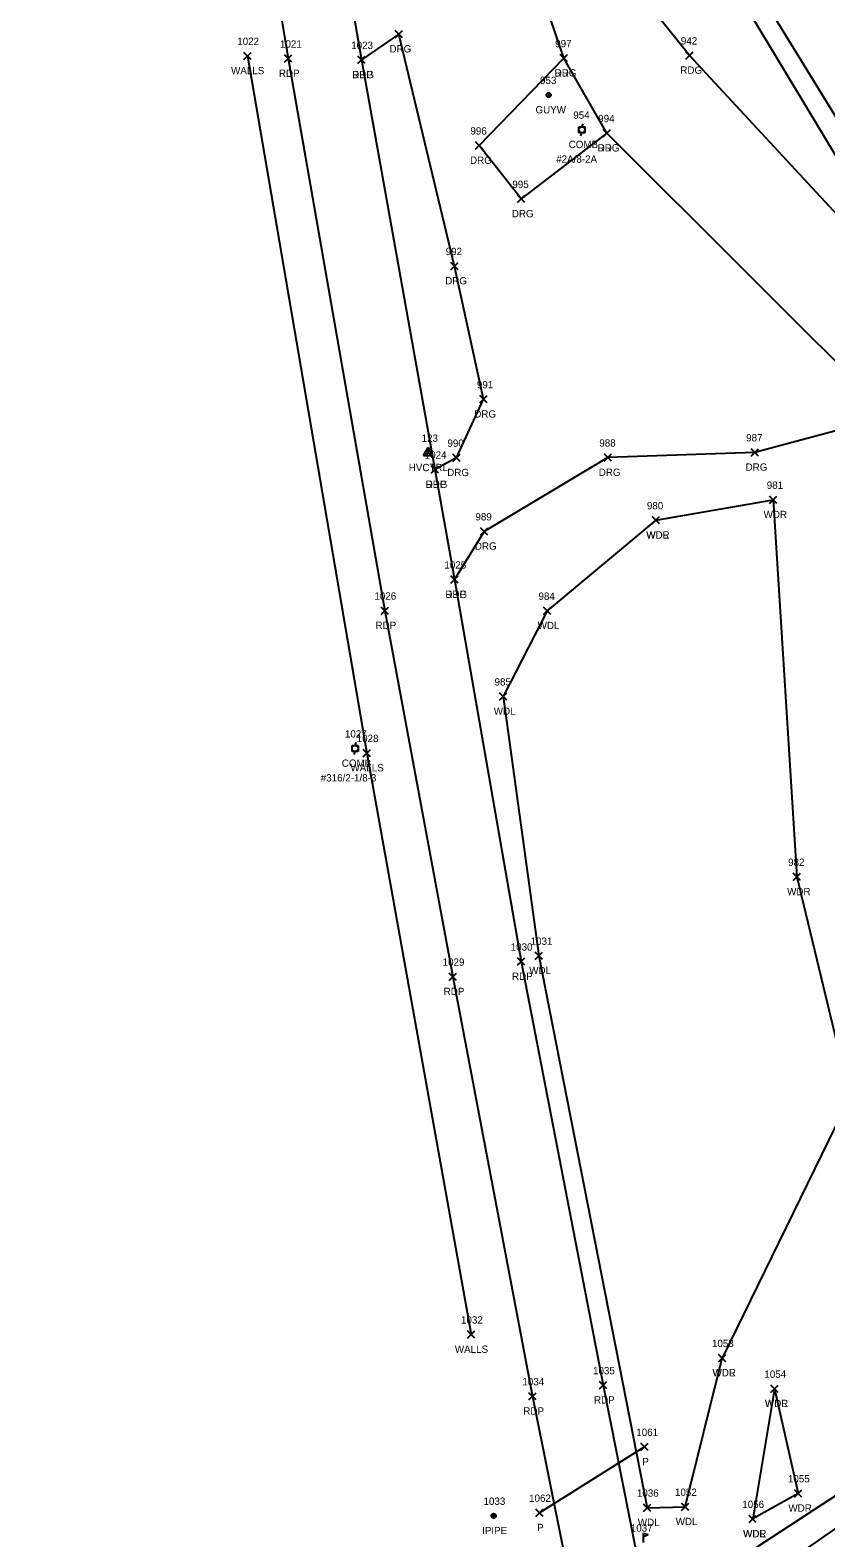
# Model space of a CAD drawing. Extents: x 1615599 to 1619911, y 273782 to 280437.
# Drawn here: x 1616094.4 to 1616311.5, y 279589.5 to 280001.3 of the extents above; entities that cross this region are included whole.
import ezdxf

# ---------------------------------------------------------------- set-up
doc = ezdxf.new("R2010")
doc.units = 0
for name, color, linetype in [('C_A', 7, 'Continuous'), ('C_I', 7, 'Continuous'), ('CPSM', 7, 'Continuous'), ('D_A', 7, 'Continuous'), ('D_I', 7, 'Continuous'), ('D_TIC', 7, 'Continuous'), ('DCP', 7, 'Continuous'), ('L_A', 7, 'Continuous'), ('L_I', 7, 'Continuous'), ('L_TIC', 7, 'Continuous'), ('LAWA', 7, 'Continuous'), ('LBC', 7, 'Continuous'), ('LBF', 7, 'Continuous'), ('LMB', 7, 'Continuous'), ('LWS', 7, 'Continuous'), ('M_A', 7, 'Continuous'), ('M_I', 7, 'Continuous'), ('MPIP', 7, 'Continuous'), ('P_A', 7, 'Continuous'), ('P_I', 7, 'Continuous'), ('P_TIC', 7, 'Continuous'), ('PET', 7, 'Continuous'), ('PEU', 7, 'Continuous'), ('R_A', 7, 'Continuous'), ('R_I', 7, 'Continuous'), ('R_TIC', 7, 'Continuous'), ('RDG', 7, 'Continuous'), ('U_A', 7, 'Continuous'), ('U_C', 7, 'Continuous'), ('U_I', 7, 'Continuous'), ('UP', 7, 'Continuous'), ('UPGW', 7, 'Continuous')]:
    doc.layers.add(name, color=color, linetype=linetype)

msp = doc.modelspace()

# ---------------------------------------------------------------- linework, layer by layer
at = {"layer": 'CPSM'}
for p, q in [((1616201.76, 279885.11), (1616203.01, 279887.27)), ((1616204.26, 279885.11), (1616203.01, 279887.27)), ((1616203.01, 279885.83), (1616203.01, 279887.27)), ((1616201.76, 279885.11), (1616203.01, 279885.83)), ((1616201.76, 279885.11), (1616204.26, 279885.11)), ((1616203.01, 279885.83), (1616203.01, 279885.83)), ((1616203.01, 279885.83), (1616204.26, 279885.11))]:
    msp.add_line(p, q, dxfattribs=at)
at = {"layer": 'D_TIC'}
for points in [[(1616261.05, 279613.33), (1616263.05, 279615.33)], [(1616263.05, 279613.33), (1616261.05, 279615.33)], [(1616232.35, 279595.34), (1616234.35, 279597.34)], [(1616234.35, 279595.34), (1616232.35, 279597.34)]]:
    msp.add_lwpolyline(points, dxfattribs=at)
at = {"layer": 'DCP'}
msp.add_lwpolyline([(1616262.05, 279614.33), (1616233.35, 279596.34)], dxfattribs=at)
at = {"layer": 'L_TIC'}
for points in [[(1616152.67, 279993.21), (1616154.67, 279995.21)], [(1616154.67, 279993.21), (1616152.67, 279995.21)], [(1616296.18, 279872), (1616298.18, 279874)], [(1616298.18, 279872), (1616296.18, 279874)], [(1616264.14, 279866.4), (1616266.14, 279868.4)], [(1616266.14, 279866.4), (1616264.14, 279868.4)], [(1616264.14, 279866.4), (1616266.14, 279868.4)], [(1616266.14, 279866.4), (1616264.14, 279868.4)], [(1616234.47, 279841.68), (1616236.47, 279843.68)], [(1616236.47, 279841.68), (1616234.47, 279843.68)], [(1616222.48, 279818.28), (1616224.48, 279820.28)], [(1616224.48, 279818.28), (1616222.48, 279820.28)], [(1616185.26, 279802.84), (1616187.26, 279804.84)], [(1616187.26, 279802.84), (1616185.26, 279804.84)], [(1616302.58, 279769.02), (1616304.58, 279771.02)], [(1616304.58, 279769.02), (1616302.58, 279771.02)], [(1616232.17, 279747.47), (1616234.17, 279749.47)], [(1616234.17, 279747.47), (1616232.17, 279749.47)], [(1616213.73, 279644.03), (1616215.73, 279646.03)], [(1616215.73, 279644.03), (1616213.73, 279646.03)], [(1616282.21, 279637.62), (1616284.21, 279639.62)], [(1616284.21, 279637.62), (1616282.21, 279639.62)], [(1616282.21, 279637.62), (1616284.21, 279639.62)], [(1616284.21, 279637.62), (1616282.21, 279639.62)], [(1616296.5, 279629.22), (1616298.5, 279631.22)], [(1616298.5, 279629.22), (1616296.5, 279631.22)], [(1616296.5, 279629.22), (1616298.5, 279631.22)], [(1616298.5, 279629.22), (1616296.5, 279631.22)], [(1616302.95, 279600.66), (1616304.95, 279602.66)], [(1616304.95, 279600.66), (1616302.95, 279602.66)], [(1616261.79, 279596.75), (1616263.79, 279598.75)], [(1616263.79, 279596.75), (1616261.79, 279598.75)], [(1616272.12, 279596.98), (1616274.12, 279598.98)], [(1616274.12, 279596.98), (1616272.12, 279598.98)], [(1616290.55, 279593.66), (1616292.55, 279595.66)], [(1616292.55, 279593.66), (1616290.55, 279595.66)], [(1616290.55, 279593.66), (1616292.55, 279595.66)], [(1616292.55, 279593.66), (1616290.55, 279595.66)]]:
    msp.add_lwpolyline(points, dxfattribs=at)
at = {"layer": 'LAWA'}
for points in [[(1616265.14, 279867.4), (1616297.18, 279873), (1616303.58, 279770.02), (1616318.08, 279709.99), (1616283.21, 279638.62)], [(1616265.14, 279867.4), (1616235.47, 279842.68), (1616223.48, 279819.28), (1616233.17, 279748.47), (1616262.79, 279597.75), (1616273.12, 279597.98), (1616283.21, 279638.62)], [(1616297.5, 279630.22), (1616291.55, 279594.66)], [(1616297.5, 279630.22), (1616303.95, 279601.66), (1616291.55, 279594.66)]]:
    msp.add_lwpolyline(points, dxfattribs=at)
at = {"layer": 'LBC'}
msp.add_lwpolyline([(1616260.86, 280142.43), (1616270.81, 280125.23), (1616271.71, 280125.76), (1616321.31, 280044.41), (1616318.76, 280042.81), (1616339.97, 280008.45), (1616336.65, 280006.38), (1616357.12, 279972.28), (1616328.36, 279954.69), (1616257.78, 280069.65), (1616226.23, 280122.19)], dxfattribs=at)
at = {"layer": 'LBF'}
msp.add_lwpolyline([(1616328.36, 279954.69), (1616323.53, 279951.52), (1616279.95, 280024.05), (1616274.42, 280020.51), (1616248.28, 280063.02), (1616257.78, 280069.65)], dxfattribs=at)
at = {"layer": 'LMB'}
for p, q in [((1616261.71, 279590.8), (1616263.01, 279590.42)), ((1616261.72, 279588.21), (1616261.72, 279590.81)), ((1616261.72, 279589.9), (1616263, 279590.41))]:
    msp.add_line(p, q, dxfattribs=at)
at = {"layer": 'LWS'}
msp.add_lwpolyline([(1616153.67, 279994.21), (1616186.26, 279803.84), (1616214.73, 279645.03)], dxfattribs=at)
at = {"layer": 'MPIP'}
for radius in [0.625, 0.0833]:
    msp.add_circle((1616220.87, 279595.52), radius, dxfattribs=at)
at = {"layer": 'P_TIC'}
for points in [[(1616163.78, 279992.49), (1616165.78, 279994.49)], [(1616165.78, 279992.49), (1616163.78, 279994.49)], [(1616183.77, 279992.13), (1616185.77, 279994.13)], [(1616185.77, 279992.13), (1616183.77, 279994.13)], [(1616239.04, 279992.6), (1616241.04, 279994.6)], [(1616241.04, 279992.6), (1616239.04, 279994.6)], [(1616273.32, 279993.35), (1616275.32, 279995.35)], [(1616275.32, 279993.35), (1616273.32, 279995.35)], [(1616250.77, 279972.13), (1616252.77, 279974.13)], [(1616252.77, 279972.13), (1616250.77, 279974.13)], [(1616203.83, 279880.25), (1616205.83, 279882.25)], [(1616205.83, 279880.25), (1616203.83, 279882.25)], [(1616209.2, 279850.21), (1616211.2, 279852.21)], [(1616211.2, 279850.21), (1616209.2, 279852.21)], [(1616190.14, 279841.72), (1616192.14, 279843.72)], [(1616192.14, 279841.72), (1616190.14, 279843.72)], [(1616227.38, 279745.88), (1616229.38, 279747.88)], [(1616229.38, 279745.88), (1616227.38, 279747.88)], [(1616208.73, 279741.75), (1616210.73, 279743.75)], [(1616210.73, 279741.75), (1616208.73, 279743.75)], [(1616249.76, 279630.19), (1616251.76, 279632.19)], [(1616251.76, 279630.19), (1616249.76, 279632.19)], [(1616230.48, 279627.16), (1616232.48, 279629.16)], [(1616232.48, 279627.16), (1616230.48, 279629.16)]]:
    msp.add_lwpolyline(points, dxfattribs=at)
at = {"layer": 'PET'}
for points in [[(1616094.39, 280432.05), (1616095.97, 280416.03), (1616096.35, 280407.62), (1616112.28, 280298.8), (1616113.01, 280288.09), (1616121.62, 280240.92), (1616154.97, 280052.02), (1616164.78, 279993.49), (1616191.14, 279842.72), (1616209.73, 279742.75), (1616231.48, 279628.16), (1616244.39, 279563.76), (1616249.99, 279537.98), (1616259.32, 279489.36)], [(1616116.33, 280409.22), (1616122.66, 280382.08), (1616122.16, 280374.78), (1616121.96, 280362.12), (1616140.8, 280248.09), (1616148.4, 280204.31), (1616173.58, 280057.29), (1616184.77, 279993.13), (1616204.83, 279881.25), (1616210.2, 279851.21), (1616228.38, 279746.88), (1616250.76, 279631.19), (1616263.33, 279567.8), (1616266.66, 279551.67), (1616278.68, 279490.29)]]:
    msp.add_lwpolyline(points, dxfattribs=at)
at = {"layer": 'PEU'}
for points in [[(1616499.74, 279780.98), (1616479.11, 279797), (1616319.46, 279945.62), (1616274.32, 279994.35), (1616255.18, 280018.22), (1616235.11, 280063.13), (1616219.63, 280113.45), (1616199.45, 280157.82), (1616176.87, 280194.27), (1616140.8, 280248.09)], [(1616486.88, 279757.56), (1616476.4, 279764.58), (1616449.89, 279788.09), (1616430.61, 279808), (1616410.01, 279827.22), (1616355.68, 279874.73), (1616329.14, 279895.83), (1616251.77, 279973.13), (1616240.04, 279993.6), (1616211.88, 280076.79), (1616204.14, 280097.8), (1616191.71, 280134.04), (1616179.76, 280157.24), (1616153.69, 280197.29), (1616148.4, 280204.31)]]:
    msp.add_lwpolyline(points, dxfattribs=at)
at = {"layer": 'R_TIC'}
for points in [[(1616193.95, 279999.18), (1616195.95, 280001.18)], [(1616195.95, 279999.18), (1616193.95, 280001.18)], [(1616183.77, 279992.13), (1616185.77, 279994.13)], [(1616185.77, 279992.13), (1616183.77, 279994.13)], [(1616239.04, 279992.6), (1616241.04, 279994.6)], [(1616241.04, 279992.6), (1616239.04, 279994.6)], [(1616250.77, 279972.13), (1616252.77, 279974.13)], [(1616252.77, 279972.13), (1616250.77, 279974.13)], [(1616215.93, 279968.75), (1616217.93, 279970.75)], [(1616217.93, 279968.75), (1616215.93, 279970.75)], [(1616227.33, 279954.16), (1616229.33, 279956.16)], [(1616229.33, 279954.16), (1616227.33, 279956.16)], [(1616209.14, 279935.83), (1616211.14, 279937.83)], [(1616211.14, 279935.83), (1616209.14, 279937.83)], [(1616217.09, 279899.46), (1616219.09, 279901.46)], [(1616219.09, 279899.46), (1616217.09, 279901.46)], [(1616291.13, 279884.95), (1616293.13, 279886.95)], [(1616293.13, 279884.95), (1616291.13, 279886.95)], [(1616209.7, 279883.48), (1616211.7, 279885.48)], [(1616211.7, 279883.48), (1616209.7, 279885.48)], [(1616209.7, 279883.48), (1616211.7, 279885.48)], [(1616211.7, 279883.48), (1616209.7, 279885.48)], [(1616251.07, 279883.53), (1616253.07, 279885.53)], [(1616253.07, 279883.53), (1616251.07, 279885.53)], [(1616203.83, 279880.25), (1616205.83, 279882.25)], [(1616205.83, 279880.25), (1616203.83, 279882.25)], [(1616217.26, 279863.37), (1616219.26, 279865.37)], [(1616219.26, 279863.37), (1616217.26, 279865.37)], [(1616209.2, 279850.21), (1616211.2, 279852.21)], [(1616211.2, 279850.21), (1616209.2, 279852.21)]]:
    msp.add_lwpolyline(points, dxfattribs=at)
at = {"layer": 'RDG'}
for points in [[(1616210.7, 279884.48), (1616218.09, 279900.46), (1616210.14, 279936.83), (1616194.95, 280000.18), (1616184.77, 279993.13)], [(1616251.77, 279973.13), (1616228.33, 279955.16), (1616216.93, 279969.75), (1616240.04, 279993.6)], [(1616329.14, 279895.83), (1616292.13, 279885.95), (1616252.07, 279884.53), (1616218.26, 279864.37), (1616210.2, 279851.21)], [(1616210.7, 279884.48), (1616204.83, 279881.25)], [(1616476.4, 279764.58), (1616476.92, 279750.96), (1616468.44, 279740.89), (1616429.63, 279704.65), (1616403.63, 279679.78), (1616362.98, 279636.29), (1616328.32, 279610.24), (1616263.33, 279567.8)], [(1616497.87, 279749.53), (1616489.21, 279745.16), (1616480.11, 279737.82), (1616436.78, 279696.31), (1616411.24, 279672.61), (1616387.47, 279642.06), (1616397.28, 279621.61), (1616371.82, 279603.44), (1616356.02, 279618.85), (1616332.01, 279604.55), (1616287.77, 279573.66), (1616275.48, 279563.53), (1616266.66, 279551.67)]]:
    msp.add_lwpolyline(points, dxfattribs=at)
at = {"layer": 'UP'}
for p, q in [((1616244.12, 279973.22), (1616244.12, 279974.89)), ((1616244.12, 279974.89), (1616245.78, 279974.89)), ((1616245.78, 279973.22), (1616244.12, 279973.22)), ((1616244.7, 279972.39), (1616244.95, 279973.22)), ((1616245.2, 279975.72), (1616244.95, 279974.89)), ((1616244.95, 279974.06), (1616244.95, 279974.06)), ((1616245.78, 279974.89), (1616245.78, 279973.22)), ((1616182.22, 279804.25), (1616182.22, 279805.92)), ((1616182.22, 279805.92), (1616183.88, 279805.92)), ((1616183.3, 279806.75), (1616183.05, 279805.92)), ((1616183.05, 279805.08), (1616183.05, 279805.08)), ((1616183.88, 279805.92), (1616183.88, 279804.25)), ((1616183.88, 279804.25), (1616182.22, 279804.25)), ((1616182.8, 279803.42), (1616183.05, 279804.25))]:
    msp.add_line(p, q, dxfattribs=at)
for centre in [(1616244.95, 279974.06), (1616183.05, 279805.08)]:
    msp.add_circle(centre, 0.833, dxfattribs=at)
at = {"layer": 'UPGW'}
for radius in [0.625, 0.0833]:
    msp.add_circle((1616235.89, 279983.55), radius, dxfattribs=at)

# ---------------------------------------------------------------- texts
at = {"layer": 'C_A'}
msp.add_text('HVCTRL', height=2, dxfattribs=at).set_placement((1616197.7, 279880.83))
at = {"layer": 'C_I'}
msp.add_text('123', height=2, dxfattribs=at).set_placement((1616201.21, 279888.83))
at = {"layer": 'D_A'}
for p in [(1616261.43, 279609.33), (1616232.73, 279591.34)]:
    msp.add_text('P', height=2, dxfattribs=at).set_placement(p)
at = {"layer": 'D_I'}
for s, p in [('1061', (1616259.8, 279617.33)), ('1062', (1616230.53, 279599.34))]:
    msp.add_text(s, height=2, dxfattribs=at).set_placement(p)
at = {"layer": 'L_A'}
for s, p in [('WALLS', (1616149.21, 279989.21)), ('WDR', (1616294.54, 279868)), ('WDR', (1616262.5, 279862.4)), ('WDL', (1616262.56, 279862.4)), ('WDL', (1616232.88, 279837.68)), ('WDL', (1616220.9, 279814.28)), ('WALLS', (1616181.8, 279798.84)), ('WDR', (1616300.95, 279765.02)), ('WDL', (1616230.58, 279743.47)), ('WALLS', (1616210.28, 279640.03)), ('WDR', (1616280.58, 279633.62)), ('WDL', (1616280.63, 279633.62)), ('WDR', (1616294.86, 279625.22)), ('WDL', (1616294.92, 279625.22)), ('WDR', (1616301.31, 279596.66)), ('WDL', (1616260.21, 279592.75)), ('WDL', (1616270.54, 279592.98)), ('WDR', (1616288.91, 279589.66)), ('WDL', (1616288.97, 279589.66))]:
    msp.add_text(s, height=2, dxfattribs=at).set_placement(p)
at = {"layer": 'L_I'}
for s, p in [('1022', (1616150.9, 279997.21)), ('981', (1616295.39, 279876)), ('980', (1616262.69, 279870.4)), ('980', (1616262.69, 279870.4)), ('984', (1616233.1, 279845.68)), ('985', (1616221.12, 279822.28)), ('1028', (1616183.49, 279806.84)), ('982', (1616301.22, 279773.02)), ('1031', (1616230.96, 279751.47)), ('1032', (1616211.96, 279648.03)), ('1053', (1616280.44, 279641.62)), ('1053', (1616280.44, 279641.62)), ('1054', (1616294.73, 279633.22)), ('1054', (1616294.73, 279633.22)), ('1036', (1616259.96, 279600.75)), ('1052', (1616270.35, 279600.98)), ('1055', (1616301.18, 279604.66)), ('1056', (1616288.72, 279597.66)), ('1056', (1616288.72, 279597.66)), ('1037', (1616258.29, 279591.2))]:
    msp.add_text(s, height=2, dxfattribs=at).set_placement(p)
at = {"layer": 'M_A'}
msp.add_text('IPIPE', height=2, dxfattribs=at).set_placement((1616217.71, 279590.52))
at = {"layer": 'M_I'}
msp.add_text('1033', height=2, dxfattribs=at).set_placement((1616218.1, 279598.52))
at = {"layer": 'P_A'}
for s, p in [('RDP', (1616162.27, 279988.49)), ('RDP', (1616182.25, 279988.13)), ('RDG', (1616237.52, 279988.6)), ('RDG', (1616271.81, 279989.35)), ('RDG', (1616249.25, 279968.13)), ('RDP', (1616202.32, 279876.25)), ('RDP', (1616207.69, 279846.21)), ('RDP', (1616188.63, 279837.72)), ('RDP', (1616225.87, 279741.88)), ('RDP', (1616207.22, 279737.75)), ('RDP', (1616248.25, 279626.19)), ('RDP', (1616228.97, 279623.16))]:
    msp.add_text(s, height=2, dxfattribs=at).set_placement(p)
at = {"layer": 'P_I'}
for s, p in [('1021', (1616162.57, 279996.49)), ('1023', (1616181.99, 279996.13)), ('997', (1616237.67, 279996.6)), ('942', (1616271.96, 279997.35)), ('994', (1616249.4, 279976.13)), ('1024', (1616202.06, 279884.25)), ('1025', (1616207.43, 279854.21)), ('1026', (1616188.32, 279845.72)), ('1030', (1616225.52, 279749.88)), ('1029', (1616206.95, 279745.75)), ('1035', (1616247.99, 279634.19)), ('1034', (1616228.71, 279631.16))]:
    msp.add_text(s, height=2, dxfattribs=at).set_placement(p)
at = {"layer": 'R_A'}
for p in [(1616192.44, 279995.18), (1616182.25, 279988.13), (1616237.52, 279988.6), (1616249.25, 279968.13), (1616214.42, 279964.75), (1616225.82, 279950.16), (1616207.63, 279931.83), (1616215.58, 279895.46), (1616289.62, 279880.95), (1616208.19, 279879.48), (1616208.19, 279879.48), (1616249.55, 279879.53), (1616202.32, 279876.25), (1616215.75, 279859.37), (1616207.69, 279846.21)]:
    msp.add_text('DRG', height=2, dxfattribs=at).set_placement(p)
at = {"layer": 'R_I'}
for s, p in [('1023', (1616181.99, 279996.13)), ('997', (1616237.67, 279996.6)), ('994', (1616249.4, 279976.13)), ('996', (1616214.52, 279972.75)), ('995', (1616225.97, 279958.16)), ('992', (1616207.78, 279939.83)), ('991', (1616216.3, 279903.46)), ('987', (1616289.77, 279888.95)), ('990', (1616208.25, 279887.48)), ('990', (1616208.25, 279887.48)), ('988', (1616249.7, 279887.53)), ('1024', (1616202.06, 279884.25)), ('989', (1616215.89, 279867.37)), ('1025', (1616207.43, 279854.21))]:
    msp.add_text(s, height=2, dxfattribs=at).set_placement(p)
at = {"layer": 'U_A'}
for s, p in [('GUYW', (1616232.29, 279978.55)), ('COMB', (1616241.34, 279969.06)), ('COMB', (1616179.43, 279800.08))]:
    msp.add_text(s, height=2, dxfattribs=at).set_placement(p)
at = {"layer": 'U_C'}
for s, p in [('#2A/8-2A', (1616237.94, 279965.06)), ('#316/2-1/8-3', (1616173.69, 279796.08))]:
    msp.add_text(s, height=2, dxfattribs=at).set_placement(p)
at = {"layer": 'U_I'}
for s, p in [('953', (1616233.53, 279986.55)), ('954', (1616242.59, 279977.06)), ('1027', (1616180.28, 279808.08))]:
    msp.add_text(s, height=2, dxfattribs=at).set_placement(p)

doc.saveas('drawing.dxf')
